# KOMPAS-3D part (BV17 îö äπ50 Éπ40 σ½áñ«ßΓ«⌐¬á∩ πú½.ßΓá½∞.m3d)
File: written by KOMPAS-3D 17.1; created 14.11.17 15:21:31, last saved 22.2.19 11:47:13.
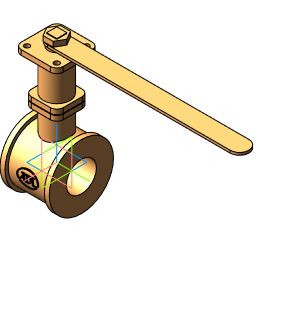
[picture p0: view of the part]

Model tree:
1. Операция без истории:1  (labels: Сталь 20  ГОСТ 1050-2013)

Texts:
  Линейный размер с обрывом
  Толщина листового тела
  Глубина освобождения сгиба
  Ширина освобождения сгиба
  BV17 МФ Ду15 Ру40 хладостойкая угл.сталь
  BV17 МФ Ду20 Ру40 хладостойкая угл.сталь
  BV17 МФ Ду25 Ру40 хладостойкая угл.сталь
  BV17 МФ Ду32 Ру40 хладостойкая угл.сталь
  BV17 МФ Ду40 Ру40 хладостойкая угл.сталь
  BV17 МФ Ду50 Ру40 хладостойкая угл.сталь
  BV17 МФ Ду65 Ру40 хладостойкая угл.сталь
  BV17 МФ Ду80 Ру40 хладостойкая угл.сталь
  BV17 МФ Ду100 Ру40 хладостойкая угл.сталь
